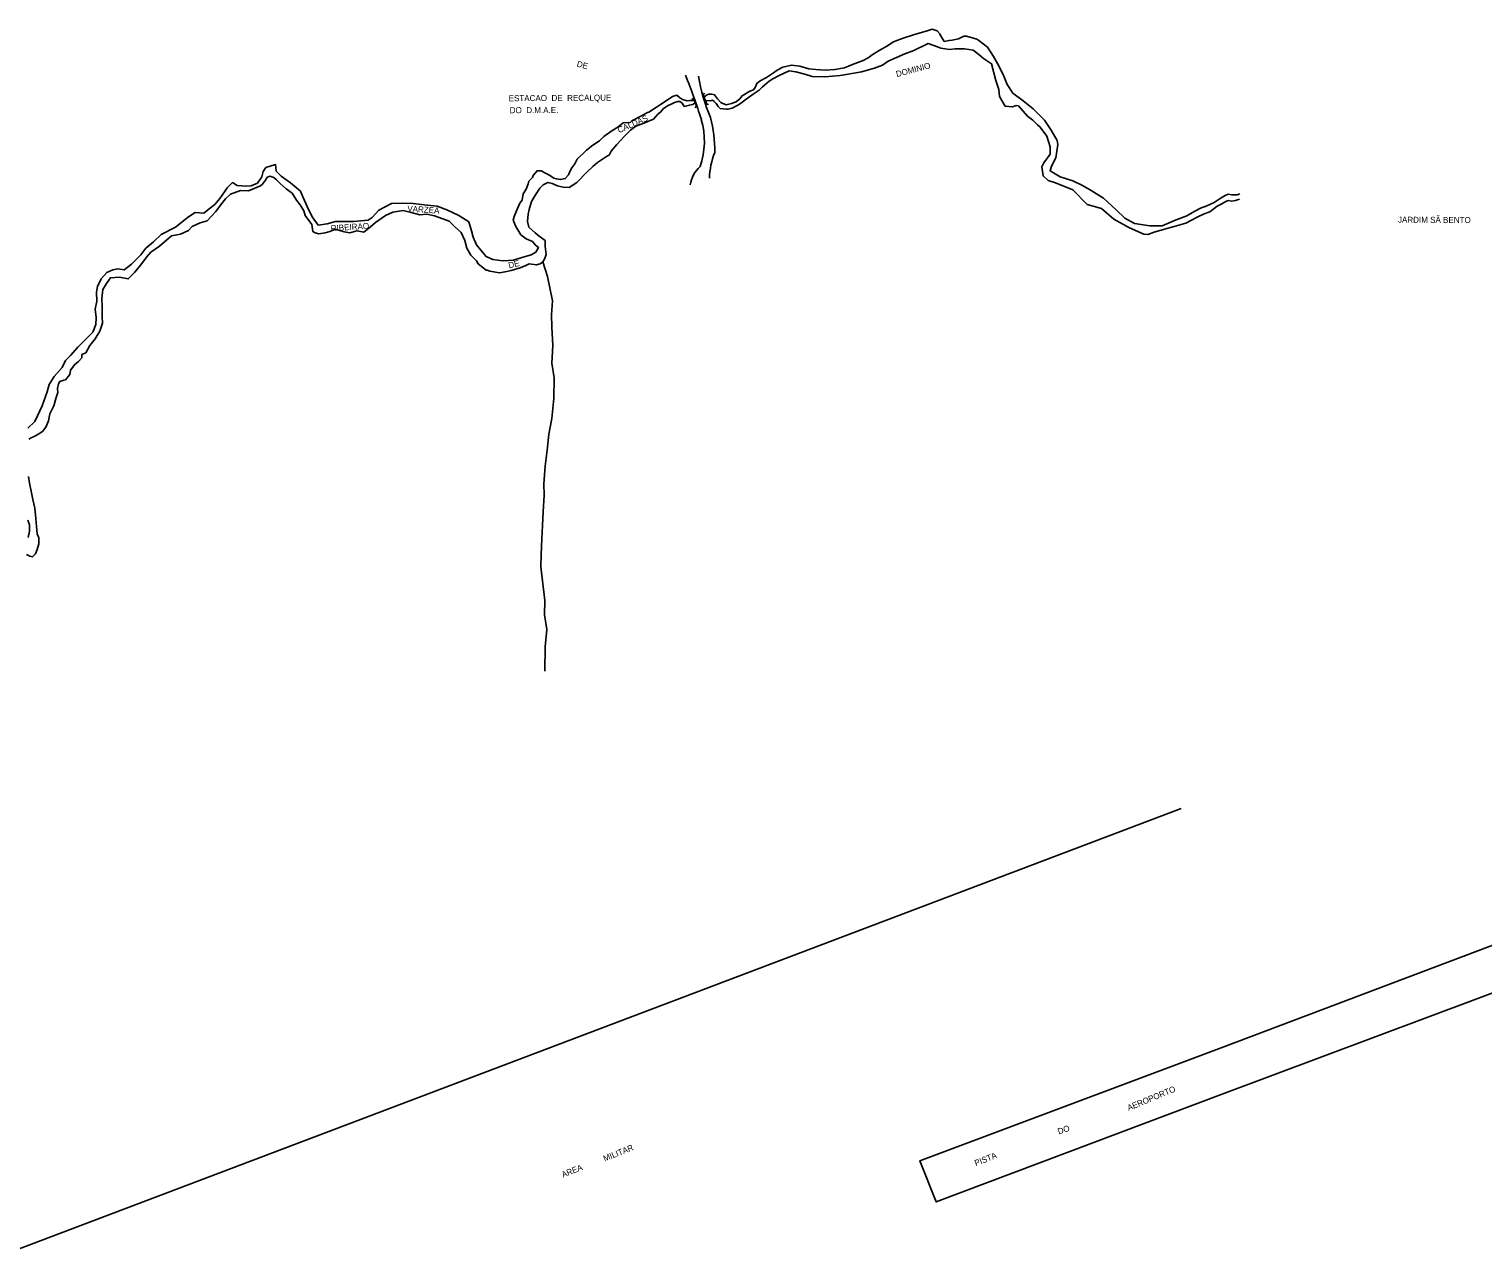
# Model space of a CAD drawing. Extents: x 325899 to 363134, y 7578590 to 7592502.
# Drawn here: x 336888 to 337856, y 7583617 to 7584429 of the extents above; entities that cross this region are included whole.
import ezdxf

# ---------------------------------------------------------------- set-up
doc = ezdxf.new("R2010")
doc.units = 0
doc.layers.add('EDIFIDENTIF', color=7, linetype='Continuous')
doc.layers.add('EDIFOBRAEXIS', color=7, linetype='Continuous')

msp = doc.modelspace()

# ---------------------------------------------------------------- linework, layer by layer
at = {"layer": 'EDIFOBRAEXIS'}
for points in [[(337681.39, 7584317.22), (337676.93, 7584313.95), (337672.02, 7584311.91), (337667.76, 7584310.18), (337663.88, 7584308.25), (337658.67, 7584305.25), (337651.57, 7584302.53), (337642.12, 7584298.57), (337634.03, 7584298.48), (337623.74, 7584300.06), (337617.32, 7584303.58), (337611.56, 7584309.1), (337603.13, 7584317.02), (337595.04, 7584322.06), (337589.13, 7584325.32), (337582.84, 7584328.36), (337574.42, 7584331.06), (337567.57, 7584335.16), (337568.6, 7584338.2), (337571.49, 7584343.66), (337572.87, 7584352.63), (337572.23, 7584355.22), (337568.37, 7584362.08), (337563.8, 7584368.74), (337556.24, 7584376.34), (337549.79, 7584381.68), (337542.89, 7584386.89), (337539.13, 7584392.57), (337536.36, 7584399.18), (337532.65, 7584406.5), (337529.98, 7584411.34), (337525.84, 7584417.35), (337520.18, 7584421.93), (337518.91, 7584422.76), (337511.94, 7584424.68), (337510.24, 7584424.78), (337506.67, 7584423), (337502.33, 7584422.03), (337500.36, 7584421.95), (337497.11, 7584421.26), (337494.42, 7584425.6), (337494.14, 7584426.31), (337492.46, 7584428.43), (337489.01, 7584429.49), (337485.14, 7584428.2), (337479.54, 7584426.62), (337476.01, 7584425.5), (337470.46, 7584423.56), (337465.68, 7584421.88), (337462.94, 7584420.84), (337459.27, 7584418.4), (337453.92, 7584415.23), (337450.86, 7584413.48), (337449.16, 7584412.33), (337446.6, 7584410.43), (337443.23, 7584408.47), (337435.98, 7584405.93), (337430.74, 7584403.59), (337424.4, 7584402.52), (337417.86, 7584402.15), (337411.75, 7584402.68), (337407.06, 7584403), (337401.1, 7584404.69), (337395.5, 7584405.47), (337389.77, 7584404.22), (337385.92, 7584402.14), (337383.39, 7584400.41), (337378.78, 7584397.26), (337374.67, 7584395.1), (337372.37, 7584393.28), (337371.36, 7584390.61), (337370.19, 7584389.09), (337367.81, 7584388.22), (337362.52, 7584385.15), (337360.97, 7584382.97), (337358.69, 7584380.99), (337355.42, 7584379.89), (337351.95, 7584379), (337349.26, 7584380.09), (337348.53, 7584380.57), (337346.12, 7584383.15), (337344.31, 7584385.76), (337342.39, 7584386.09), (337340.33, 7584386.09), (337339.4, 7584385.6), (337337.34, 7584384.41)], [(337338.36, 7584381.83), (337341.43, 7584381.65), (337342.87, 7584382.08), (337343.89, 7584381.27), (337345.28, 7584379.93), (337346.66, 7584377.86), (337348.08, 7584376.69), (337352.01, 7584376.09), (337353.35, 7584376.27), (337356.04, 7584376.9), (337359.79, 7584378.73), (337361.58, 7584380), (337365.33, 7584382.87), (337370.02, 7584386.15), (337373.95, 7584388.76), (337376, 7584390.8), (337380.58, 7584394.88), (337383.01, 7584396.46), (337387.29, 7584398.49), (337393.83, 7584401.59), (337398.39, 7584400.94), (337404.43, 7584399.4), (337409.32, 7584397.86), (337417.72, 7584397.59), (337427.8, 7584398.54), (337433.1, 7584399.38), (337442.05, 7584401.02), (337450.82, 7584403.41), (337456.01, 7584405.42), (337459.76, 7584408.14), (337470.81, 7584413.02), (337476.94, 7584415.23), (337486.36, 7584419.78), (337492.6, 7584417.76), (337494.94, 7584416.7), (337500.62, 7584415.89), (337504.34, 7584416.23), (337510.71, 7584416.36), (337516.39, 7584415.51), (337520.22, 7584412.47), (337523.24, 7584409.99), (337528.72, 7584406.37), (337531.39, 7584395.32), (337533.53, 7584389.16), (337533.89, 7584384.63), (337537.68, 7584378.12), (337542.57, 7584377.79), (337544.98, 7584378.56), (337546.55, 7584378.33), (337552.64, 7584371.57), (337556.17, 7584368.84), (337559.16, 7584365.77), (337561.04, 7584364.28), (337565.51, 7584358.2), (337567.72, 7584351.15), (337567.76, 7584346.16), (337563.4, 7584340.43), (337562.11, 7584337.79), (337562.98, 7584331.75), (337566.23, 7584328.74), (337571.25, 7584327.18), (337582.69, 7584322.53), (337592.31, 7584312.6), (337601.77, 7584310), (337610.04, 7584302.96), (337620.45, 7584297.17), (337629.98, 7584292.92), (337632.65, 7584292.7), (337636.98, 7584294.17), (337643.72, 7584296.36), (337650.13, 7584297.97), (337657.91, 7584300.36), (337661.69, 7584302.17), (337665.99, 7584304.45), (337670.2, 7584306.43), (337673.9, 7584307.88), (337678.91, 7584311.49), (337681.39, 7584313.01)], [(337330.35, 7584381.97), (337327.69, 7584381.91), (337326.07, 7584381.73), (337322.87, 7584382.52), (337321.02, 7584384.01), (337319.24, 7584385.43), (337316.33, 7584384.59), (337313.46, 7584382.56), (337308.35, 7584379.18), (337305.61, 7584377.55), (337300.52, 7584374.27), (337299.51, 7584373.87), (337295.58, 7584371.68), (337289.17, 7584368.46), (337288.11, 7584367.36), (337283.52, 7584367.08), (337279.92, 7584364.21), (337275.89, 7584361.72), (337270.63, 7584358.06), (337267.61, 7584355.14), (337263.23, 7584352.12), (337258.98, 7584348.95), (337252.9, 7584342.78), (337251.15, 7584339.79), (337249.23, 7584337.05), (337248.04, 7584335.04), (337247.13, 7584332.4), (337244.83, 7584329.94), (337241.69, 7584329.25), (337238.95, 7584329.76), (337237.22, 7584330.31), (337235.78, 7584331.38), (337233.44, 7584332.64), (337231.21, 7584333.7), (337228.72, 7584335.15), (337226.11, 7584335.12), (337223.4, 7584331.94), (337223, 7584330.65), (337220.65, 7584328.21), (337220.22, 7584326.39), (337218.83, 7584322.94), (337216.9, 7584319.82), (337216.1, 7584315.66), (337214.63, 7584313.6), (337212.41, 7584308.53), (337210.79, 7584304.75), (337210.23, 7584302.22), (337211.86, 7584298.04), (337215.24, 7584292.54), (337218.77, 7584289.75), (337222.95, 7584288.11), (337225.16, 7584285.71), (337227.06, 7584284.01), (337225.17, 7584280.89), (337222.2, 7584279.16), (337215.38, 7584277.15), (337210.39, 7584275.52), (337203.37, 7584275.21), (337196.73, 7584275.99), (337192.11, 7584277.98), (337188.56, 7584282.19), (337185.79, 7584285.91), (337183.6, 7584290.85), (337182.48, 7584295.13), (337180.73, 7584301.09), (337174.1, 7584305.39), (337165.94, 7584309.21), (337159.52, 7584311.58), (337150.97, 7584312.44), (337143.57, 7584313.47), (337136.42, 7584313.56), (337129.15, 7584313.25), (337120.66, 7584308.9), (337116.33, 7584304.08), (337113.59, 7584302.27), (337103.94, 7584301.35), (337097.32, 7584301.27), (337091.84, 7584301.39), (337086.42, 7584299.83), (337080.46, 7584298.89), (337076.35, 7584304.51), (337073.1, 7584311.38), (337070.38, 7584317.43), (337070.17, 7584317.86), (337068.67, 7584321.49), (337061.85, 7584327.13), (337055.81, 7584331.53), (337052.38, 7584334.95), (337052.07, 7584339.24), (337045.63, 7584337.38), (337043.71, 7584334.64), (337042.85, 7584331.11), (337039.94, 7584326.9), (337035.79, 7584325.1), (337032.7, 7584324.81), (337026.54, 7584325.24), (337023.34, 7584327.26), (337019.79, 7584323.73), (337018.07, 7584321.04), (337014.86, 7584316.6), (337011.57, 7584312.67), (337007.77, 7584309.8), (337004.32, 7584306.93), (336998.39, 7584307.38), (336994.01, 7584304.56), (336985.42, 7584297.5), (336975.8, 7584292.65), (336970.73, 7584287.9), (336965.74, 7584283.64), (336962.38, 7584279.12), (336956.02, 7584273.03), (336951.18, 7584269.24), (336947.03, 7584269.77), (336943.6, 7584269.11), (336939.63, 7584267.41), (336935.91, 7584263.17), (336933.4, 7584258.12), (336932.92, 7584254.42), (336933.01, 7584248.36), (336931.95, 7584242.93), (336932.62, 7584237.38), (336932.29, 7584232.74), (336930.42, 7584227.62), (336926.52, 7584223.96), (336920.42, 7584217.79), (336915.59, 7584212.26), (336912.27, 7584208.84), (336909.87, 7584204.17), (336904.65, 7584198.25), (336901.39, 7584192.75), (336899.87, 7584187.91), (336896.59, 7584178.57), (336893.45, 7584171.93), (336891.71, 7584168.17), (336887.2, 7584163.81)], [(336887.77, 7584156.56), (336889.36, 7584157.27), (336891.77, 7584158.46), (336894.38, 7584160.01), (336896.94, 7584161.64), (336899.12, 7584164.4), (336900.86, 7584168.61), (336901.82, 7584173.36), (336904.4, 7584178.73), (336905.96, 7584184.16), (336907.02, 7584187.48), (336906.87, 7584190.15), (336907.57, 7584193.26), (336908.43, 7584194.94), (336911.02, 7584195.63), (336912.11, 7584195.93), (336915.02, 7584199.41), (336915.42, 7584202.43), (336918.31, 7584206.21), (336920.86, 7584208.09), (336923.02, 7584210.67), (336923.06, 7584212.73), (336925.65, 7584213.92), (336928.46, 7584218.87), (336932, 7584223.26), (336934.93, 7584228.26), (336936.85, 7584233.61), (336936.52, 7584238.1), (336936.49, 7584244.71), (336936.38, 7584250.21), (336937.08, 7584256.1), (336939.43, 7584260.15), (336942.04, 7584263.81), (336948.12, 7584264.27), (336953.93, 7584263.14), (336958.23, 7584267.63), (336963.07, 7584273.52), (336966.06, 7584277.63), (336968.94, 7584280.95), (336974.84, 7584285.04), (336982.74, 7584291.77), (336988.65, 7584293.02), (336993.95, 7584295.33), (336996.5, 7584298.02), (337001.72, 7584300.49), (337006.49, 7584301.81), (337012.28, 7584308.11), (337015.42, 7584312.17), (337018.64, 7584316.48), (337022.08, 7584319.65), (337028.59, 7584322.05), (337033.89, 7584321.82), (337042.05, 7584325.03), (337043.27, 7584326.25), (337044.38, 7584327.77), (337045.44, 7584329.14), (337046.25, 7584330.59), (337048.15, 7584331.6), (337050.76, 7584330.59), (337052.74, 7584329.05), (337055.1, 7584326.67), (337059.06, 7584323.2), (337063.05, 7584320.24), (337065.97, 7584315.65), (337068.41, 7584312.49), (337070.84, 7584308.43), (337071.68, 7584305.29), (337076.18, 7584299.47), (337076.84, 7584294.65), (337078.44, 7584293.87), (337080.75, 7584293.18), (337085.11, 7584293.8), (337088.13, 7584294.69), (337092, 7584296.19), (337097.63, 7584294.57), (337101.36, 7584293.84), (337106.12, 7584295.17), (337110.69, 7584294.29), (337115.12, 7584297.92), (337118.49, 7584300.61), (337125.28, 7584305.26), (337130.12, 7584307.54), (337136.86, 7584308.67), (337142.21, 7584307.43), (337148.07, 7584305.89), (337152.71, 7584306.33), (337157.9, 7584305.09), (337163.38, 7584303.07), (337167.54, 7584301.68), (337171.04, 7584298.06), (337175.56, 7584294.16), (337178.05, 7584288.82), (337179.45, 7584283.57), (337181.97, 7584279.01), (337185.68, 7584275.26), (337186.97, 7584273.24), (337192.22, 7584269.04), (337192.81, 7584269.04), (337194.76, 7584268.35), (337201.07, 7584267.09), (337204.75, 7584267.91), (337208.96, 7584268.68), (337214.94, 7584270.63), (337218.51, 7584272.11), (337220.79, 7584273.18), (337225.68, 7584272.57), (337228.14, 7584273.29), (337230.04, 7584274.41), (337231.08, 7584276.31), (337232.19, 7584279.3), (337231.5, 7584284.73), (337231.42, 7584288.68), (337227.51, 7584291.72), (337224.92, 7584293.84), (337220.71, 7584297.64), (337219.64, 7584301.34), (337220.27, 7584306.23), (337220.85, 7584309.33), (337222.34, 7584314.73), (337225.07, 7584319.04), (337227.95, 7584323.53), (337230.23, 7584325.77), (337233.37, 7584327.37), (337236.16, 7584326.71), (337239.71, 7584325.22), (337243.36, 7584324.29), (337247.45, 7584324.01), (337252.46, 7584327.24), (337259.32, 7584334.25), (337263.32, 7584337.98), (337266.31, 7584340.74), (337272.95, 7584344.99), (337274.06, 7584345.65), (337275.51, 7584348.18), (337279.2, 7584352.75), (337284.37, 7584358.13), (337288.34, 7584362.14), (337291.79, 7584364.83), (337297.26, 7584366.94), (337303.54, 7584369.59), (337306.76, 7584373.09), (337308.18, 7584374.11), (337310.1, 7584376.42), (337312.86, 7584378.32), (337315.78, 7584379.79), (337317.68, 7584380.58), (337319.73, 7584381.19), (337321.1, 7584381.35), (337322.67, 7584380.08), (337324.09, 7584378.03), (337327.64, 7584378.85), (337329.77, 7584379.33), (337331.14, 7584380.37)], [(337329.21, 7584383.26), (337330.35, 7584382.88), (337332.2, 7584378.34), (337331.34, 7584377.15)], [(337340.14, 7584379.17), (337339, 7584379.6), (337336.68, 7584385.63), (337337.62, 7584386.79)], [(337681.39, 7584317.22), (337684.27, 7584318.66), (337686.16, 7584319.47), (337688.69, 7584319.02), (337692.22, 7584319.11), (337694.01, 7584319.87)], [(337681.39, 7584313.01), (337684.99, 7584314.81), (337686.42, 7584315.3), (337688.4, 7584314.99), (337691.01, 7584315.25), (337693.72, 7584316.27)], [(337230.04, 7584274.41), (337233.02, 7584264.7), (337236.26, 7584248.53), (337235.61, 7584239.28), (337235.9, 7584230.99), (337236.7, 7584218.92), (337235.88, 7584207), (337237.49, 7584197.35), (337237.25, 7584183.58), (337235.92, 7584170.3), (337233.93, 7584159.7), (337232.71, 7584149.17), (337231.55, 7584138.5), (337230.63, 7584126.63), (337230.79, 7584119.23), (337230.2, 7584108.05), (337229.62, 7584098.95), (337229.25, 7584090.08), (337228.79, 7584079.58), (337228.64, 7584071.52), (337231.23, 7584048.93), (337230.99, 7584039.43), (337232.52, 7584029.8), (337231.42, 7584018.21), (337231.21, 7584001.91)], [(336886.27, 7584079.72), (336888.35, 7584078.63), (336890.1, 7584078.12), (336892.15, 7584080.05), (336893.39, 7584082.89), (336894.42, 7584086.85), (336894.44, 7584090.78), (336893.4, 7584093.49), (336892.86, 7584098.23), (336892.4, 7584103.68), (336891.68, 7584110.45), (336890.48, 7584116.18), (336889.38, 7584121.73), (336888.31, 7584127.07), (336887.65, 7584131.69)], [(336887.07, 7584102.48), (336888.29, 7584099.47), (336888.1, 7584095.11), (336887.37, 7584090.95)], [(337681.39, 7583720.06), (338434.73, 7584001.91)], [(336881.39, 7583617.31), (337654.81, 7583910.54)], [(338021.46, 7583879.6), (337681.39, 7583751.17)], [(337681.39, 7583720.06), (337491.79, 7583648.66), (337481.01, 7583676.04), (337681.39, 7583751.17)]]:
    msp.add_lwpolyline(points, dxfattribs=at)
for centre, radius, start, end in [((336967.43, 7584254.86), 385.37, 17.25872, 21.9423), ((337439.54, 7584413.98), 107.07, 188.53998, 203.83387), ((337286.2, 7584354.86), 51.28, 340.81804, 16.22133), ((337247.96, 7584347.59), 96.46, 359.86064, 13.8723), ((337392, 7584328.39), 51.23, 158.271, 178.05851), ((337349.54, 7584321.99), 21.88, 132.92272, 170.09943)]:
    msp.add_arc(centre, radius, start, end, dxfattribs=at)

# ---------------------------------------------------------------- texts
at = {"layer": 'EDIFIDENTIF'}
for s, rotation, p in [('DE', 345.13563, (337252.2, 7584404.6)), ('DOMINIO', 14.8024, (337465.61, 7584397.51)), ('ESTACAO  DE  RECALQUE', 0.309, (337207.17, 7584381.45)), ('DO  D.M.A.E.', 0.15267, (337207.91, 7584373.48)), ('CALDAS', 23.88232, (337280.75, 7584360.14)), ('VARZEA', 356.22003, (337139.61, 7584308.01)), ('RIBEIRAO', 3.86373, (337088.89, 7584294.84)), ('JARDIM SAÕ BENTO', 359.76993, (337799.2, 7584300.56)), ('DE', 13.00686, (337207.48, 7584270.14)), ('AEROPORTO', 22.56354, (337619.97, 7583709.19)), ('DO', 18.60905, (337573.46, 7583693.51)), ('MILITAR', 21.57675, (337271.1, 7583675.5)), ('PISTA', 21.654, (337518.25, 7583672.36)), ('AREA', 21.5588, (337243.3, 7583664.71))]:
    msp.add_text(s, height=4, rotation=rotation, dxfattribs=at).set_placement(p)

doc.saveas('drawing.dxf')
